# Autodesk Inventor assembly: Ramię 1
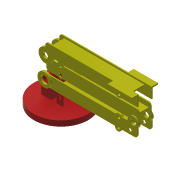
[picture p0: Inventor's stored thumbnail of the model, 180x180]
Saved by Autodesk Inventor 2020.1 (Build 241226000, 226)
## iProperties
Manager: www.cadconsulting.pl
Company: Fabian Stasiak CAD Consulting
Created: 2005-10
Part Number: Ramię 1
Document SubType Name: Assembly
Designer: F.Stasiak
Author: F.Stasiak
Subject: Zbiór ćwiczeń. Autodesk Inventor 2020. Kurs podstawowy
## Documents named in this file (5)
- C:\2020_Kurs_podstawowy\R6 Zespoły\Sterowanie\Ramię 1.iam
- C:\2020_Kurs_podstawowy\R6 Zespoły\Sterowanie\Podstawa.ipt
- C:\2020_Kurs_podstawowy\R6 Zespoły\Sterowanie\R1.ipt
- C:\2020_Kurs_podstawowy\R6 Zespoły\Sterowanie\R2.ipt
- C:\2020_Kurs_podstawowy\R6 Zespoły\Sterowanie\R3.ipt
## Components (4 placed, 4 different names)
1. Podstawa:1 — Wstaw:1, NAPĘD
2. R1:1 — Wstaw:1, NAPĘD, Wstaw:2, Kąt:2
3. R2:1 — Wstaw:2, Kąt:2, Wstaw:3, Kąt:3
4. R3:1 — Wstaw:3, Kąt:3
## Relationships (6: Insert 3, Angle 3)
- Wstaw:1 [Insert]: Podstawa:1 ↔ R1:1
- NAPĘD [Angle]: Podstawa:1 ↔ R1:1
- Wstaw:2 [Insert]: R1:1 ↔ R2:1
- Kąt:2 [Angle]: R1:1 ↔ R2:1
- Wstaw:3 [Insert]: R2:1 ↔ R3:1
- Kąt:3 [Angle]: R2:1 ↔ R3:1
